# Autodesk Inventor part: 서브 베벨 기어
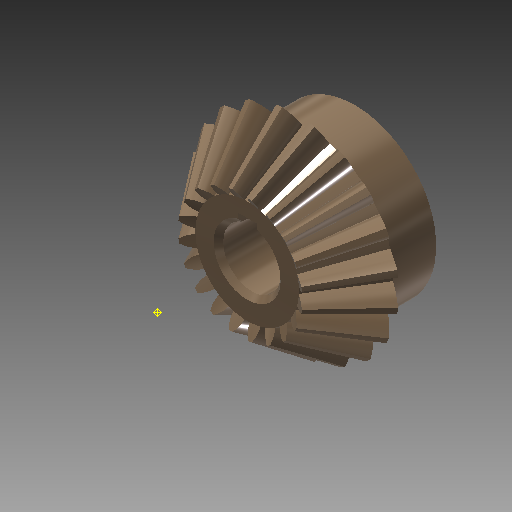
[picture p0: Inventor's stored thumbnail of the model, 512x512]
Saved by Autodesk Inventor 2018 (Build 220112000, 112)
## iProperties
Created: 2016-04
Part Number: 서브 베벨 기어
Material: 강철, 탄소
Document SubType Name: Modeling
Designer: mdu
Categories: <?xml version="1.0" encoding="UTF-16"?> <MemberInstance><Categories><FamilyTemplate><FamilyTemplateParameter ValueType="xs:double" Id="1" ObjectReferenceKey="da
Mass: 135.037 g
Surface Area: 63.6518 cm^2
Volume: 17.1585 cm^3
Density: 7.87 g/cm^3
Appearance: 얼룩무늬
CustomPartVersion: 1
Author: mdu
Revision Number: 1
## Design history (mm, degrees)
node "맨 위 점"
node "메쉬 평면2"
sketch "톱니 본체 스케치"
  geometry: L1 (0, 0)-(18.003, -31.331); L2 (18.003, -31.331)-(21.664, -28.891); L3 (21.664, -28.891)-(0, 0); L4 (20, -30)-(0, 0); L5 (10.813, -18.818)-(13.012, -17.352); L6 (18.003, -31.331)-(10.813, -18.818); L7 (21.664, -28.891)-(13.012, -17.352); L8 (0, -39.387)-(0, 6.564) reference; L9 (0, -30)-(21.664, -30)
  constraints: 16 end point, 4 point on line, 3 perpendicular, 2 collinear, 1 horizontal alignment, 1 vertical alignment
  dimensions: "d0" = 40 diameter of L4.start L8 (= da_de); "d1" = 36.00616 diameter of L1.end L8 (= da_dfe); "d2" = 43.3282 diameter of L2.end L8 (= da_dae); "d3" = 14.4 distance between parallel lines of L2 L5 (= da_b); "d4" = 28.8906 vertical distance of L2.end L1.start (= da_ve)
revolve "톱니 본체" sketch "톱니 본체 스케치" stored, may be unused: angle "d5" = 90 deg
node "시작점"
node "톱니 평면"
sketch "시작 스케치"
  geometry: L1 (0, -23.505)-(0, 10.645) reference; L2 (-0.834, -2.928)-(0.834, -2.928); A1 r 8.898 centre (-9.698, -3.713) between (-0.834, -2.928) and (-3.903, 3.04); A2 r 8.898 centre (9.698, -3.713) between (3.903, 3.04) and (0.834, -2.928); A3 r 27.357 centre (0, -24.037) between (3.903, 3.04) and (-3.903, 3.04); 1 further point
  constraints: 6 point on circle, 3 centre point, 3 symmetric about line, 2 end point, 1 coincident, 1 perpendicular, 1 other
  dimensions: "d7" = 8.89846 radius of A1 (= fd_rr); "d8" = 9.69794 horizontal distance of point (0, -24.037) A1.centre (= fd_x); "d9" = 20.32439 vertical distance of point (0, -24.037) A1.centre (= fd_y); "d57" = 27.35701 radius of A3 (= 0.5 x fd_dva + 0.3 x da_he); "d58" = 21.10901 distance from line of A3.centre L2 (= 0.5 x fd_dva - 1.12 x da_he)
node "끝점"
  node "끝 평면"
sketch "3D 스케치 오른쪽"
  node "Helical Curve Right" dims "d65" = 229.90621 (computed from da_dm, da_delta, da_beta), "d66" = 31.5, "d67" = 40 (= da_de), "d68" = -5.88003 (= -da_delta), "d69" = 12.16458 (computed from fd_loft, da_delta)
node "끝 평면 오른쪽"
sketch "끝 스케치 오른쪽"
  geometry: L1 (0, -22.649)-(0, 12.15) reference; L2 (-0.497, -1.72)-(0.497, -1.72); A1 r 5.299 centre (-5.775, -2.187) between (-0.497, -1.72) and (-2.324, 1.834); A2 r 5.299 centre (5.775, -2.187) between (2.324, 1.834) and (0.497, -1.72); A3 r 16.291 centre (0, -14.29) between (2.324, 1.834) and (-2.324, 1.834); 1 further point
  constraints: 6 point on circle, 3 centre point, 3 symmetric about line, 2 end point, 1 coincident, 1 perpendicular, 1 other
  dimensions: "d70" = 5.77526 horizontal distance of A3.centre A1.centre (computed from fd_x, fd_ratio); "d71" = 12.10346 vertical distance of point (0, -14.29) A1.centre (computed from fd_y, fd_ratio); "d72" = 5.29916 radius of A1 (computed from fd_rr, fd_ratio); "d73" = 12.57071 distance from line of point (0, -14.29) L2 (computed from d58, fd_ratio); "d74" = 16.29149 radius of A3 (computed from d57, fd_ratio)
feature "로프트 오른쪽" sketch "끝 스케치 오른쪽" dims "d75" = 0, "d77" = 0, "d79" = 0, "d80" = 90 deg, "d85" = 20, "d92" = 90 deg, "d93" = 90 deg, "da_teethtype" = 0 [user parameter]
sketch "3D 스케치 왼쪽"
  node "Helical Curve Left" dims "d26" = 229.90621 (computed from da_dm, da_delta, da_beta), "d27" = 12.16458 (computed from fd_loft, da_delta), "d28" = 40 (= da_de), "d29" = -5.88003 (= -da_delta)
node "끝 평면 왼쪽"
sketch "끝 스케치 왼쪽" dims "d56" = 10.82768 (derived)
  geometry: L1 (0, -35.087)-(0, 18.089) reference; L2 (-0.497, -1.716)-(0.497, -1.716); A1 r 5.299 centre (-5.775, -2.183) between (-0.497, -1.716) and (-2.324, 1.838); A2 r 5.299 centre (5.775, -2.183) between (2.324, 1.838) and (0.497, -1.716); A3 r 16.291 centre (0, -14.287) between (2.324, 1.838) and (-2.324, 1.838); 2 further points; 1 other entity
  constraints: 6 point on circle, 3 centre point, 3 symmetric about line, 2 end point, 1 coincident, 2 other
  dimensions: "d30" = 5.29916 radius of A1 (computed from fd_rr, fd_ratio); "d31" = 5.77526 horizontal distance of point (0, -14.287) A1.centre (computed from fd_x, fd_ratio); "d32" = 12.10346 vertical distance of A1.centre point (0, -14.287) (computed from fd_y, fd_ratio); "d61" = 16.29149 radius of A3 (computed from d57, fd_ratio); "d62" = 12.57071 distance from line of point (0, -14.287) L2 (computed from d58, fd_ratio)
feature "로프트 왼쪽" sketch "끝 스케치 왼쪽" dims "d35" = 0, "d37" = 0, "d39" = 0, "d40" = 90 deg, "d84" = 10, "d90" = 90 deg, "d91" = 90 deg, "da_teethtype" = 0 [user parameter]
sketch "본체 스케치"
  geometry: L1 (0, -35.038)-(0, -19.531) reference; L2 (18.003, -31.331)-(10.813, -18.818) reference; L3 (10.813, -18.818)-(0, -18.818); L4 (18.003, -31.331)-(0, -31.331)
  constraints: 4 end point, 2 perpendicular, 2 point on line
revolve "본체 고정" sketch "본체 스케치" stored, may be unused: angle "d46" = 90 deg
feature "피치 지름" dims angle "d47" = 90 deg
sketch "스케치8"
  geometry: C1 r 17 at (0, 0); 1 further point
  constraints: 1 centre point, 1 coincident
  dimensions: "d94" = 34 diameter of C1
extrude "돌출1" join sketch "스케치8" distance "d95" = 10; taper "d96" = 0 deg
sketch "스케치9"
  geometry: 1 further point
hole "구멍1" sketch "스케치9" at (0, 0) diameter "d97" = 12; stored, may be unused: countersink angle "d101" = 90 deg, drill point angle "d103" = 118 deg; dims "d98" = 6, "d99" = 4, "d100" = 2, "d102" = 8
sketch "스케치10"
  geometry: 1 further point
sketch "스케치11"
  geometry: 1 further point
sketch "스케치12"
  geometry: L1 (-2, 5.657)-(-2, 7.8); L2 (-2, 7.8)-(2, 7.8); L3 (2, 7.8)-(2, 5.657); A1 r 6 centre (0, 0) between (-2, 5.657) and (2, 5.657) reference; 1 further point
  constraints: 6 end point, 2 parallel, 2 point on circle, 1 perpendicular, 1 vertical
  dimensions: "d104" = 4 distance of L1.end L2.end; "d105" = 13.8 dimension on A1 L2
extrude "돌출2" cut sketch "스케치12" extent not by distance; stored distance "d106" = 7; taper "d107" = 0 deg
chamfer "모따기1" distance "d108" = 1; stored, may be unused: second distance "d109" = 2, angle "d110" = 45 deg
body "Solid1"
feature "로프트" dims "d17" = 0, "d18" = 90 deg, "d19" = 0, "d20" = 90 deg, "d89" = 0, "da_teethtype" = 0 [user parameter]
pattern_circular "원형 패턴" dims angle "d22" = 360 deg, "d88" = 0, "da_teethtype" = 0 [user parameter]
pattern_circular "원형 패턴 오른쪽" dims angle "d82" = 360 deg, "da_teethtype" = 0 [user parameter]
pattern_circular "원형 패턴 왼쪽" dims angle "d42" = 360 deg, "da_teethtype" = 0 [user parameter]
sketch "끝 스케치"
  geometry: L1 (0, -15.359)-(0, 6.983) reference; L2 (-0.497, -1.72)-(0.497, -1.72); A1 r 5.299 centre (-5.775, -2.187) between (-0.497, -1.72) and (-2.324, 1.834); A2 r 5.299 centre (5.775, -2.187) between (2.324, 1.834) and (0.497, -1.72); A3 r 16.291 centre (0, -14.29) between (2.324, 1.834) and (-2.324, 1.834); 1 further point
  constraints: 6 point on circle, 3 centre point, 3 symmetric about line, 2 end point, 1 coincident, 1 other
  dimensions: "d12" = 5.29916 radius of A1 (computed from fd_rr, fd_ratio); "d15" = 5.77526 horizontal distance of A1.centre point (0, -14.29) (computed from fd_x, fd_ratio); "d16" = 12.10346 vertical distance of A1.centre point (0, -14.29) (computed from fd_y, fd_ratio); "d59" = 16.29149 radius of A3 (computed from d57, fd_ratio); "d60" = 12.57071 distance from line of A3.centre L2 (computed from d58, fd_ratio)
sketch "Sketch6"
  geometry: L1 (20, -30)-(0, 0) reference; L2 (0, -37.8)-(0, 6.3) reference
body "Srf1"
other parameters: "da_b" = 14.4 [user parameter; used in 2 equation terms], "da_de" = 40 [user parameter; used in 4 equation terms], "da_dae" = 43.3282 [user parameter; used in 2 equation terms], "da_dfe" = 36.00616 [user parameter; used in 1 equation term], "da_le" = 36.05551 [user parameter; used in 1 equation term], "da_omega" = 90 deg [user parameter; used in 1 equation term], "da_beta" = 0 [user parameter; used in 2 equation terms], "da_delta" = 5.88003 [user parameter; used in 8 equation terms], "da_alpha" = 20 deg [user parameter; used in 2 equation terms], "da_he" = 4.4 [user parameter; used in 4 equation terms], "da_ve" = 28.8906 [user parameter; used in 1 equation term], "fd_dv" = 48.07402 (computed from da_de, da_delta) [user parameter; used in 1 equation term], "fd_dva" = 52.07402 (computed from da_dae, da_delta) [user parameter; used in 3 equation terms], "fd_dvb" = 45.1748 (computed from fd_dv, da_alpha) [user parameter; used in 2 equation terms], "da_zv" = 240.37008 [user parameter; used in 1 equation term], "fd_loft" = 14.62 (= da_b + 0.05 x da_he) [user parameter; used in 4 equation terms], "fd_ratio" = 5.95514 (computed from da_le, fd_loft) [user parameter; used in 15 equation terms], "fd_rr" = 8.89846 (computed from fd_dd, fd_dvb) [user parameter; used in 6 equation terms], "fd_angle" = 0.66075 (computed from da_zv) [user parameter; used in 4 equation terms], "fd_x1" = 1.58709 (computed from da_dvw, fd_angle) [user parameter; used in 1 equation term], "fd_y1" = 23.98456 (computed from da_dvw, fd_angle) [user parameter; used in 1 equation term], "fd_x2" = 8.11084 (computed from fd_rr, fd_angle2, fd_angle) [user parameter; used in 1 equation term], "fd_y2" = 3.66016 (computed from fd_rr, fd_angle2, fd_angle) [user parameter; used in 1 equation term], "fd_x" = 9.69794 (= fd_x1 + fd_x2) [user parameter; used in 4 equation terms], "fd_y" = 20.32439 (= fd_y1 - fd_y2) [user parameter; used in 4 equation terms], "fd_angle2" = 3.57832 (computed from fd_dvb, fd_dd, da_alpha) [user parameter; used in 2 equation terms], "fd_dd" = 48.55402 (= fd_dva - 0.8 x da_he) [user parameter; used in 2 equation terms], "da_dvw" = 48.07402 [user parameter; used in 2 equation terms], "d11" = 14.62 (= fd_loft), "da_dm" = 32.01232 [user parameter; used in 2 equation terms], "da_x" = 0 [user parameter], "da_m" = 2 [user parameter], "d48" = 0, "d49" = 0, "d50" = 90 deg (= da_omega), "d51" = 9 deg (computed from da_z), "d52" = 0, "d53" = 0, "d54" = 0
